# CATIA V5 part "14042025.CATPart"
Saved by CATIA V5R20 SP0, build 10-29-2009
Part number: 14042025
Definition: NONE
Nomenclature: 14042025
Source: Unknown
Description: 14042025
Bounding box of the stored display mesh (mm): x -12.5 to 50, y -35 to 24.917, z -25.1 to 25.1
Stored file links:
  C:\Users\Utente\Desktop\IO LAVORO\3D X SITO CF\X SITO\PLASTICA\RF2\14042025.CATPart
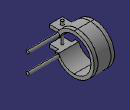
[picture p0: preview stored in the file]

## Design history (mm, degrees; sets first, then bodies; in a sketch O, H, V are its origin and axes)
Body1 "14042025" (main body)
  Solid1: solid without history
